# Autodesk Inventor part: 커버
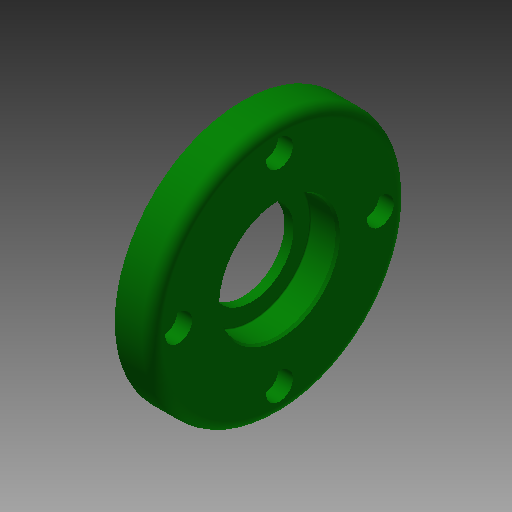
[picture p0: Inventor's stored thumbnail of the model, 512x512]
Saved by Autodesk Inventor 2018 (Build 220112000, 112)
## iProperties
Created: 2018-11
Part Number: 커버
Material: 알루미늄 6061
Document SubType Name: Modeling
Designer: mduedu
Density: 1 g/cm^3
Appearance: 진녹색
Author: mduedu
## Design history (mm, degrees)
revolve "회전1" stored, may be unused: angle "d7" = 90 deg
revolve "회전2" stored, may be unused: angle "d14" = 90 deg
fillet "모깎기1" dims "d15" = 0.3
chamfer "모따기1" distance "d16" = 0.8; stored, may be unused: second distance "d17" = 2, angle "d18" = 30 deg
fillet "모깎기2" dims "d19" = 1, "d35" = 3
chamfer "모따기2" distance "d20" = 0.5; stored, may be unused: second distance "d21" = 2, angle "d22" = 30 deg
sketch "스케치5" dims "d55" = 60
  geometry: 3 further points
  constraints: 2 vertical alignment, 1 coincident, 2 other
hole "구멍3" sketch "스케치5" at (0, 30) diameter "d56" = 4.5; stored, may be unused: countersink angle "d60" = 90 deg, drill point angle "d62" = 118 deg; dims "d57" = 6, "d58" = 8, "d59" = 4.4, "d61" = 8
node "솔리드1"
pattern_circular "원형 패턴1" dims angle "d64" = 360 deg
sketch "스케치1"
  geometry: L1 (0, 0)-(3, 0); L2 (3, 23.5)-(0, 23.5); L3 (0, 23.5)-(0, 0); L4 (3, 0)-(9, 0); L5 (11, 38)-(3, 38); L6 (3, 38)-(3, 23.5); L7 (9, 0)-(14, 0); L8 (14, 0)-(14, 35); A1 r 3 centre (11, 35) between (14, 35) and (11, 38)
  constraints: 16 end point, 3 horizontal, 2 parallel, 2 point on circle, 2 tangent, 1 centre point, 1 perpendicular, 1 vertical
  dimensions: "d0" = 76 diameter of L5 L4; "d3" = 47 diameter of L2 L1; "d6" = 14 distance between parallel lines of L8 L3; "d46" = 3 distance between parallel lines of L6 L3; "d47" = 3 radius of A1
sketch "스케치2"
  geometry: L1 (0, -23.5)-(0, 23.5) reference; L2 (0, 23.5)-(3, 23.5) reference; L3 (3, 23.5)-(3, 38) reference; L4 (3, 38)-(11, 38) reference; L5 (11, -38)-(3, -38) reference; L6 (3, -38)-(3, -23.5) reference; L7 (3, -23.5)-(0, -23.5) reference; L8 (0, 0)-(3, 0); L9 (3, 0)-(3, 20); L10 (3, 20)-(0, 20); L11 (0, 20)-(0, 0); L12 (3, 0)-(5.7, 0); L13 (5.7, 0)-(5.7, 12.5); L14 (5.7, 12.5)-(3, 12.5); L15 (3, 12.5)-(3, 0); L16 (5.7, 0)-(14, 0); L17 (14, 0)-(14, 17.5); L18 (14, 17.5)-(5.7, 17.5); L19 (5.7, 17.5)-(5.7, 0); L20 (14, 35)-(14, -35) reference; A1 r 3 centre (11, 35) between (14, 35) and (11, 38) reference; A2 r 3 centre (11, -35) between (11, -38) and (14, -35) reference
  constraints: 24 end point, 6 parallel, 3 horizontal, 3 perpendicular
  dimensions: "d8" = 35 diameter of L18 L16; "d10" = 25 diameter of L14 L12; "d11" = 40 diameter of L10 L8; "d12" = 3 distance of L9.end L10.end; "d13" = 8.3 distance of L17.end L18.end
node "절단 모서리 투영1"
